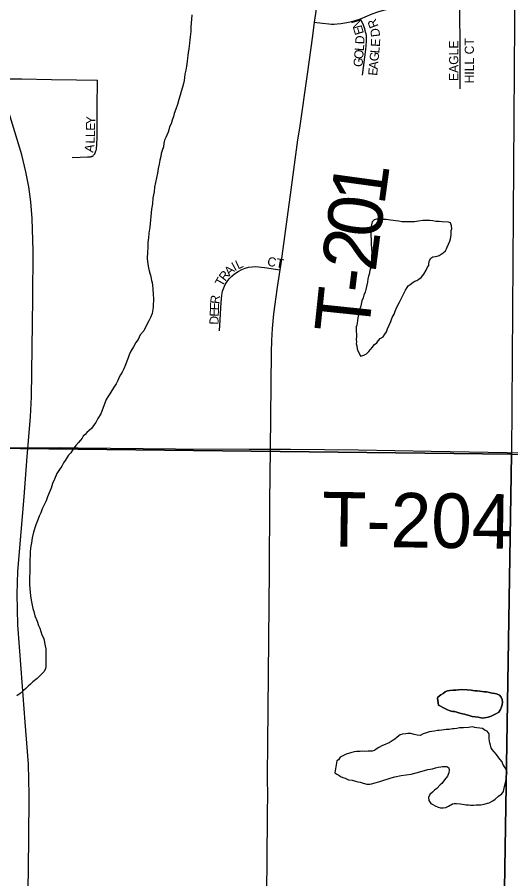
# Model space of a CAD drawing. Extents: x 0 to 68, y 0 to 52.9.
# Drawn here: x 43.794 to 44.473, y 38.666 to 39.851 of the extents above; entities that cross this region are included whole.
import ezdxf

# ---------------------------------------------------------------- set-up
doc = ezdxf.new("R2010")
doc.units = 0
for name, color, linetype in [('Default', 7, 'Continuous'), ('GM_X_Minor_Lake', 7, 'Continuous'), ('GM_X_Minor_River', 7, 'Continuous'), ('GM_X_Township_Road', 7, 'Continuous'), ('GM_X_Township_Road_Text', 7, 'Continuous'), ('GM_X_Township_Subdivision', 7, 'Continuous'), ('GM_X_Township_Subdivision_Text', 7, 'Continuous')]:
    doc.layers.add(name, color=color, linetype=linetype)

msp = doc.modelspace()

# ---------------------------------------------------------------- linework, layer by layer
at = {"layer": 'Default'}
for points in [[(44.4829, 40.5718), (44.4735, 39.2501), (43.1609, 39.2654), (43.1833, 40.5874)], [(43.1609, 39.2654), (44.4735, 39.2501), (44.4523, 37.939), (44.4103, 37.9396), (43.1327, 37.9528)], [(45.7998, 39.2161), (45.7821, 37.907), (45.7586, 37.9073), (44.4523, 37.939), (44.4735, 39.2501)]]:
    msp.add_lwpolyline(points, close=True, dxfattribs=at)
for points in [[(44.2659, 39.8493), (44.2819, 39.8561), (44.2897, 39.8588), (44.2976, 39.8611), (44.3057, 39.8629), (44.3138, 39.864), (44.322, 39.8646), (44.3463, 39.8653)], [(44.403, 39.7527), (44.4028, 39.7866), (44.4028, 39.8071), (44.4025, 39.8648)], [(44.2023, 39.8444), (44.2134, 39.8432), (44.2222, 39.8423), (44.2262, 39.8419), (44.2297, 39.842), (44.2336, 39.8422), (44.2386, 39.8428), (44.2469, 39.8442), (44.2558, 39.8461), (44.2659, 39.8493)], [(44.2687, 39.7718), (44.2732, 39.8068), (44.2743, 39.8181), (44.2743, 39.8206), (44.2741, 39.8237), (44.2739, 39.8261), (44.2735, 39.8287), (44.2729, 39.8309), (44.2716, 39.8352), (44.2698, 39.8404), (44.2659, 39.8493)], [(43.7391, 39.767), (43.7505, 39.7668), (43.7998, 39.7666), (43.8409, 39.7657), (43.8751, 39.7654), (43.9042, 39.7647)], [(43.8992, 39.662), (43.9003, 39.6636), (43.9009, 39.6649), (43.9014, 39.6662), (43.9018, 39.6673), (43.9023, 39.6685), (43.9026, 39.6695), (43.9027, 39.6701), (43.9028, 39.6712), (43.9029, 39.6721), (43.903, 39.6743), (43.9032, 39.6771), (43.9034, 39.6853), (43.9036, 39.704), (43.9038, 39.727), (43.9042, 39.7647)], [(43.8073, 38.5411), (43.8097, 38.7192), (43.8103, 38.7814), (43.8092, 38.8237), (43.8045, 38.8814), (43.7993, 38.9545), (43.7947, 39.0153), (43.7935, 39.0576), (43.7946, 39.0885), (43.8033, 39.1914), (43.8075, 39.2467), (43.812, 39.3017), (43.8135, 39.3289), (43.8152, 39.4639), (43.8154, 39.5301), (43.8142, 39.5746), (43.8124, 39.5973), (43.8095, 39.6179), (43.8056, 39.6387), (43.7999, 39.6618), (43.7776, 39.736)], [(43.8694, 39.6584), (43.8803, 39.6589), (43.8902, 39.6591), (43.8919, 39.6592), (43.8927, 39.6592), (43.8937, 39.6593), (43.8944, 39.6593), (43.8952, 39.6595), (43.8961, 39.6597), (43.8969, 39.6601), (43.8975, 39.6604), (43.898, 39.6608), (43.8987, 39.6614), (43.8992, 39.662)], [(43.6153, 39.2601), (43.7344, 39.2593), (43.8246, 39.2588), (43.8532, 39.2591), (43.8579, 39.2589)]]:
    msp.add_lwpolyline(points, dxfattribs=at)
at = {"layer": 'GM_X_Minor_Lake'}
for points in [[(44.387, 39.5695), (44.3784, 39.5697), (44.3784, 39.5697), (44.3739, 39.5703), (44.3694, 39.5704), (44.3654, 39.571), (44.3614, 39.5716), (44.3579, 39.5716), (44.3549, 39.5717), (44.3514, 39.5718), (44.3458, 39.5709), (44.3403, 39.57), (44.3338, 39.5696), (44.3278, 39.5697), (44.3227, 39.5698), (44.3188, 39.5709), (44.3147, 39.571), (44.3107, 39.5716), (44.3072, 39.5721), (44.3037, 39.5727), (44.3012, 39.5728), (44.2947, 39.5729), (44.2912, 39.5735), (44.2882, 39.5735), (44.2847, 39.5726), (44.2821, 39.5696), (44.281, 39.5656), (44.2805, 39.5632), (44.2804, 39.5601), (44.2804, 39.5576), (44.2803, 39.5551), (44.2803, 39.5526), (44.2802, 39.5496), (44.2806, 39.5466), (44.2805, 39.5421), (44.2805, 39.5391), (44.2809, 39.5331), (44.2813, 39.5275), (44.2811, 39.5215), (44.281, 39.5155), (44.2804, 39.51), (44.2798, 39.506), (44.2788, 39.503), (44.2782, 39.5005), (44.2776, 39.4975), (44.2771, 39.495), (44.276, 39.4915), (44.2754, 39.487), (44.2743, 39.481), (44.2732, 39.4765), (44.2721, 39.473), (44.2705, 39.4691), (44.2695, 39.4651), (44.2679, 39.4611), (44.2668, 39.4566), (44.2657, 39.4526), (44.2646, 39.4491), (44.2635, 39.4456), (44.263, 39.4421), (44.2624, 39.4376), (44.2618, 39.4341), (44.2612, 39.4306), (44.2607, 39.4276), (44.2601, 39.4251), (44.2601, 39.4221), (44.2604, 39.4121), (44.2598, 39.4081), (44.2602, 39.4046), (44.2601, 39.4021), (44.2606, 39.3991), (44.2615, 39.395), (44.262, 39.3925), (44.2639, 39.389), (44.2658, 39.3849), (44.2704, 39.3863), (44.2739, 39.3883), (44.2775, 39.3912), (44.2796, 39.3942), (44.2821, 39.3971), (44.2852, 39.4011), (44.2883, 39.4035), (44.2903, 39.406), (44.2929, 39.4094), (44.297, 39.4114), (44.2995, 39.4153), (44.3016, 39.4183), (44.3032, 39.4228), (44.3053, 39.4277), (44.3074, 39.4327), (44.3095, 39.4382), (44.3121, 39.4427), (44.3137, 39.4471), (44.3159, 39.4526), (44.3195, 39.4591), (44.3242, 39.4685), (44.3263, 39.473), (44.3279, 39.4759), (44.3299, 39.4794), (44.3315, 39.4819), (44.334, 39.4838)], [(44.334, 39.4838), (44.3381, 39.4868), (44.3407, 39.4882), (44.3432, 39.4892), (44.3462, 39.4911), (44.3493, 39.4931), (44.3529, 39.498), (44.356, 39.5035), (44.3581, 39.5074), (44.3597, 39.5099), (44.3597, 39.5124), (44.3608, 39.5164), (44.3624, 39.5199), (44.3654, 39.5218), (44.3689, 39.5223), (44.3715, 39.5227), (44.374, 39.5237), (44.377, 39.5251), (44.3796, 39.5271), (44.3826, 39.53), (44.3842, 39.5325), (44.3852, 39.535), (44.3889, 39.5434), (44.3895, 39.5464), (44.3906, 39.5514), (44.3907, 39.5544), (44.3907, 39.5579), (44.3913, 39.5604), (44.3909, 39.5644), (44.3899, 39.5685), (44.387, 39.5695)], [(44.4608, 38.905), (44.4614, 38.909), (44.4609, 38.9126), (44.4595, 38.9156), (44.457, 38.9187), (44.4531, 38.9202), (44.4506, 38.9208), (44.4471, 38.9214), (44.4431, 38.922), (44.4391, 38.923), (44.4366, 38.9231), (44.4331, 38.9237), (44.4301, 38.9242), (44.4265, 38.9243), (44.4235, 38.9244), (44.4205, 38.9249), (44.418, 38.9255), (44.4125, 38.9256), (44.4045, 38.9262), (44.397, 38.9254), (44.3935, 38.9255), (44.3889, 38.9251), (44.3854, 38.9246), (44.3824, 38.9232), (44.3798, 38.9207), (44.3763, 38.9188), (44.3722, 38.9159), (44.3717, 38.9144)], [(44.3717, 38.9144), (44.3722, 38.9159), (44.3763, 38.9188), (44.3798, 38.9207), (44.3824, 38.9232), (44.3854, 38.9246), (44.3889, 38.9251), (44.3935, 38.9255), (44.397, 38.9254), (44.4045, 38.9262), (44.4125, 38.9256), (44.418, 38.9255), (44.4205, 38.9249), (44.4235, 38.9244), (44.4265, 38.9243), (44.4301, 38.9242), (44.4331, 38.9237), (44.4366, 38.9231), (44.4391, 38.923), (44.4431, 38.922), (44.4471, 38.9214), (44.4506, 38.9208), (44.4531, 38.9202), (44.457, 38.9187), (44.4595, 38.9156), (44.4609, 38.9126), (44.4614, 38.909), (44.4608, 38.905), (44.4597, 38.9026), (44.4586, 38.8986), (44.4561, 38.8951), (44.453, 38.8932), (44.4495, 38.8912), (44.4454, 38.8898), (44.4414, 38.8884), (44.4363, 38.8875), (44.4338, 38.887), (44.4278, 38.8882), (44.4193, 38.8893), (44.4153, 38.8904), (44.4118, 38.8915), (44.4088, 38.8921), (44.4063, 38.8926), (44.4023, 38.8937), (44.3984, 38.8953), (44.3954, 38.8958), (44.3929, 38.8959), (44.3904, 38.8964), (44.3879, 38.8975), (44.3854, 38.8985), (44.3819, 38.9001), (44.3789, 38.9017), (44.376, 38.9032), (44.373, 38.9048), (44.3717, 38.9144)], [(44.3717, 38.9144), (44.373, 38.9048), (44.376, 38.9032), (44.3789, 38.9017), (44.3819, 38.9001), (44.3854, 38.8985), (44.3879, 38.8975), (44.3904, 38.8964), (44.3929, 38.8959), (44.3954, 38.8958), (44.3984, 38.8953), (44.4023, 38.8937), (44.4063, 38.8926), (44.4088, 38.8921), (44.4118, 38.8915), (44.4153, 38.8904), (44.4193, 38.8893), (44.4278, 38.8882), (44.4338, 38.887), (44.4363, 38.8875), (44.4414, 38.8884), (44.4454, 38.8898), (44.4495, 38.8912), (44.453, 38.8932), (44.4561, 38.8951), (44.4586, 38.8986), (44.4597, 38.9026), (44.4608, 38.905)], [(44.4058, 38.7687), (44.4088, 38.7682), (44.4113, 38.7676), (44.4143, 38.7676), (44.4173, 38.767), (44.4213, 38.7669), (44.4249, 38.7674), (44.4314, 38.7677), (44.4359, 38.7686), (44.4405, 38.77), (44.443, 38.7705), (44.4481, 38.7729), (44.4511, 38.7754), (44.4557, 38.7793), (44.4603, 38.7827), (44.4624, 38.7857), (44.4629, 38.7882), (44.464, 38.7926), (44.4651, 38.7961), (44.4657, 38.8001), (44.4668, 38.8041), (44.4668, 38.8081), (44.4674, 38.8116), (44.4665, 38.8152), (44.465, 38.8187), (44.4616, 38.8233), (44.4607, 38.8268), (44.4582, 38.8299), (44.4563, 38.8324), (44.4529, 38.837), (44.4499, 38.8406), (44.447, 38.8436), (44.4455, 38.8462), (44.4446, 38.8497), (44.4437, 38.8527), (44.4432, 38.8553), (44.4428, 38.8588), (44.4428, 38.8623), (44.4429, 38.8653), (44.44, 38.8689), (44.4375, 38.8699), (44.4335, 38.8725), (44.43, 38.8731), (44.426, 38.8737), (44.423, 38.8742), (44.42, 38.8748), (44.417, 38.8743), (44.4145, 38.8739), (44.4075, 38.8735), (44.4044, 38.8736), (44.4019, 38.8736), (44.3984, 38.8727), (44.3949, 38.8723), (44.3924, 38.8723), (44.3878, 38.8714), (44.3838, 38.871), (44.3808, 38.8706), (44.3773, 38.8701), (44.3743, 38.8697), (44.3718, 38.8697), (44.3677, 38.8688), (44.3642, 38.8684), (44.3602, 38.868), (44.3566, 38.8665), (44.3521, 38.8651), (44.3481, 38.8632), (44.344, 38.8633), (44.3395, 38.8644), (44.3351, 38.8655), (44.331, 38.8655), (44.328, 38.8651), (44.3235, 38.8647), (44.3205, 38.8637), (44.3164, 38.8608), (44.3133, 38.8579), (44.3108, 38.8564), (44.3082, 38.8545), (44.3052, 38.853), (44.3007, 38.8511), (44.2951, 38.8487), (44.291, 38.8463), (44.2875, 38.8443), (44.2849, 38.8424), (44.2819, 38.8414), (44.2789, 38.8415), (44.2764, 38.8416), (44.2719, 38.8411), (44.2693, 38.8412), (44.2653, 38.8408), (44.2628, 38.8408), (44.2603, 38.8409), (44.2573, 38.8404), (44.2538, 38.8395), (44.2462, 38.8372), (44.2381, 38.8333), (44.2355, 38.8293), (44.2333, 38.8281)], [(44.2333, 38.8281), (44.2306, 38.8114), (44.2331, 38.8098), (44.2361, 38.8083), (44.2385, 38.8067), (44.2415, 38.8052), (44.245, 38.8041), (44.2495, 38.802), (44.2545, 38.8014), (44.259, 38.8003), (44.262, 38.7992), (44.2655, 38.7986), (44.2695, 38.7976), (44.2745, 38.796), (44.2785, 38.7959), (44.281, 38.7963), (44.286, 38.7977), (44.2926, 38.7996), (44.3082, 38.8048), (44.3133, 38.8062), (44.3219, 38.808), (44.3289, 38.8089), (44.3354, 38.8098), (44.3475, 38.813), (44.3586, 38.8163), (44.3647, 38.8172), (44.3692, 38.8186), (44.3728, 38.8196), (44.3763, 38.82), (44.3788, 38.8204), (44.3823, 38.8204), (44.3848, 38.8203), (44.3873, 38.8183), (44.3877, 38.8152), (44.3876, 38.8117), (44.3866, 38.8093), (44.3855, 38.8068), (44.3814, 38.8018), (44.3778, 38.7969), (44.3753, 38.7949), (44.3711, 38.79), (44.3676, 38.7876), (44.365, 38.7851), (44.3614, 38.7817), (44.3594, 38.7777), (44.3598, 38.7737), (44.3627, 38.7696), (44.3652, 38.7681), (44.3687, 38.766), (44.3726, 38.7644), (44.3761, 38.7633), (44.3796, 38.7633), (44.3832, 38.7637), (44.3867, 38.7656), (44.3923, 38.769), (44.3948, 38.7695), (44.3978, 38.7694), (44.4033, 38.7688), (44.4058, 38.7687)]]:
    msp.add_lwpolyline(points, dxfattribs=at)
at = {"layer": 'GM_X_Minor_River'}
for points in [[(44.034, 39.8545), (44.0327, 39.8375), (44.0326, 39.8319), (44.032, 39.8279), (44.0314, 39.8244), (44.0313, 39.8204), (44.0308, 39.8159), (44.0302, 39.8119), (44.0296, 39.8074), (44.029, 39.8029), (44.0284, 39.7989), (44.0278, 39.7949), (44.0272, 39.7904), (44.0266, 39.7839), (44.0255, 39.7784), (44.0244, 39.7729), (44.0238, 39.7684), (44.0232, 39.7644), (44.0226, 39.7604), (44.021, 39.7549), (44.0194, 39.749), (44.0178, 39.744), (44.0161, 39.738), (44.014, 39.7315), (44.0119, 39.725), (44.0097, 39.7191), (44.0086, 39.7146), (44.007, 39.7096), (44.0054, 39.7046), (44.0033, 39.7006), (44.0022, 39.6966), (44.0012, 39.6932), (43.9996, 39.6892), (43.998, 39.6857), (43.9964, 39.6822), (43.9954, 39.6782), (43.9947, 39.6732), (43.9931, 39.6682), (43.9915, 39.6638), (43.991, 39.6598), (43.9899, 39.6548), (43.9887, 39.6493), (43.9876, 39.6433), (43.9865, 39.6368), (43.9854, 39.6303), (43.9837, 39.6238), (43.9826, 39.6173), (43.982, 39.6113), (43.9803, 39.6028), (43.9796, 39.5948), (43.9785, 39.5873), (43.9759, 39.5623), (43.9748, 39.5543), (43.9741, 39.5478), (43.9735, 39.5412), (43.9734, 39.5347), (43.9727, 39.5282), (43.9726, 39.5192), (43.9734, 39.5117), (43.9743, 39.5066), (43.9752, 39.5026), (43.9762, 39.4991), (43.9771, 39.4965), (43.978, 39.492), (43.9785, 39.489), (43.9794, 39.4865), (43.9798, 39.4824), (43.9802, 39.4774), (43.9806, 39.4699), (43.981, 39.4644), (43.9809, 39.4604), (43.9808, 39.4574), (43.9808, 39.4528), (43.9802, 39.4493), (43.9791, 39.4438), (43.9769, 39.4384), (43.9748, 39.4334), (43.9717, 39.4274), (43.968, 39.42), (43.9629, 39.4141), (43.9598, 39.4081), (43.9567, 39.4037), (43.9535, 39.3977), (43.9499, 39.3918), (43.9478, 39.3868), (43.9462, 39.3828), (43.9446, 39.3783), (43.9425, 39.3729), (43.9404, 39.3674), (43.9378, 39.3629), (43.9357, 39.3595), (43.9341, 39.356), (43.932, 39.3515)], [(43.932, 39.3515), (43.9299, 39.347), (43.9268, 39.3426), (43.9237, 39.3376), (43.9211, 39.3332), (43.9185, 39.3292), (43.916, 39.3253), (43.9085, 39.3058), (43.9044, 39.2994), (43.9018, 39.2939), (43.8987, 39.2895), (43.8961, 39.286), (43.8925, 39.2826), (43.8895, 39.2797), (43.8869, 39.2772), (43.8843, 39.2747), (43.8828, 39.2723), (43.8807, 39.2693), (43.8781, 39.2663), (43.8745, 39.2619), (43.872, 39.2589), (43.8699, 39.2555), (43.8673, 39.252), (43.8642, 39.2486), (43.8617, 39.2451), (43.8596, 39.2416), (43.8575, 39.2382), (43.8549, 39.2337), (43.8518, 39.2288), (43.8482, 39.2233), (43.845, 39.2159), (43.8424, 39.2099), (43.8402, 39.2034), (43.8376, 39.1969), (43.8355, 39.1915), (43.8334, 39.186), (43.8308, 39.1805), (43.8281, 39.1751), (43.826, 39.1696), (43.8239, 39.1646), (43.8218, 39.1596), (43.8192, 39.1527), (43.8159, 39.1427), (43.8143, 39.1352), (43.8131, 39.1282), (43.812, 39.1212), (43.8114, 39.1147), (43.8113, 39.1102), (43.8112, 39.1057), (43.8111, 39.1007), (43.811, 39.0972), (43.8109, 39.0927), (43.8108, 39.0877), (43.8107, 39.0806), (43.8106, 39.0756), (43.8105, 39.0701), (43.8109, 39.0651), (43.8117, 39.055), (43.813, 39.049), (43.8144, 39.0424), (43.8153, 39.0379), (43.8167, 39.0334), (43.8181, 39.0278), (43.821, 39.0202), (43.8229, 39.0142), (43.8248, 39.0106), (43.8262, 39.0061), (43.8276, 39.0016), (43.8296, 38.9975), (43.8305, 38.994), (43.8314, 38.9909), (43.8323, 38.9864), (43.8328, 38.9824), (43.8331, 38.9754), (43.833, 38.9694), (43.8329, 38.9628), (43.8328, 38.9578), (43.8327, 38.9548), (43.8301, 38.9504), (43.826, 38.9464), (43.8209, 38.9415), (43.8153, 38.9366), (43.8117, 38.9337), (43.8086, 38.9307), (43.8056, 38.9278), (43.8025, 38.9248), (43.7979, 38.9209), (43.7933, 38.9175)]]:
    msp.add_lwpolyline(points, dxfattribs=at)
at = {"layer": 'GM_X_Township_Road'}
for points in [[(44.2126, 39.9141), (44.2023, 39.8444)], [(44.2023, 39.8444), (44.1997, 39.8257), (44.1925, 39.7729), (44.1819, 39.6989)], [(44.1819, 39.6989), (44.1794, 39.6827), (44.1702, 39.6137), (44.1562, 39.5124), (44.1549, 39.5036)], [(44.1549, 39.5036), (44.1513, 39.4799), (44.1463, 39.4434), (44.1442, 39.4231), (44.1433, 39.4067), (44.143, 39.3903), (44.1418, 39.2568)], [(43.8579, 39.2589), (43.8777, 39.2587)], [(43.8777, 39.2587), (44.0115, 39.2574), (44.1126, 39.257), (44.1418, 39.2568)], [(44.1418, 39.2568), (44.1409, 39.1843), (44.1401, 39.09), (44.1379, 38.8521), (44.1376, 38.8077), (44.138, 38.7767), (44.1376, 38.7612), (44.1368, 38.6836), (44.1357, 38.6017), (44.1348, 38.4829), (44.1338, 38.4295), (44.1326, 38.3229), (44.1314, 38.2573), (44.1303, 38.1835), (44.1274, 38.0358), (44.126, 37.9797), (44.1264, 37.9556), (44.1266, 37.9518), (44.1273, 37.949), (44.1301, 37.9455)], [(44.1418, 39.2568), (44.1694, 39.2568), (44.2632, 39.2561), (44.363, 39.2544), (44.4678, 39.2526), (44.6184, 39.2499), (44.7894, 39.2463), (44.806, 39.2462)]]:
    msp.add_lwpolyline(points, dxfattribs=at)
at = {"layer": 'GM_X_Township_Subdivision'}
msp.add_lwpolyline([(44.0717, 39.4196), (44.0728, 39.4351), (44.0742, 39.4589), (44.0751, 39.4687), (44.0762, 39.4744), (44.0777, 39.479), (44.0798, 39.4835), (44.0824, 39.4877), (44.0854, 39.4916), (44.0889, 39.4951), (44.0927, 39.4982), (44.0974, 39.5016), (44.1025, 39.5043), (44.1071, 39.5061), (44.1118, 39.5073), (44.1167, 39.508), (44.1216, 39.5082), (44.1257, 39.508), (44.1339, 39.5069), (44.1549, 39.5036)], dxfattribs=at)

# ---------------------------------------------------------------- texts
at = {"layer": 'Default'}
for s, rotation, p in [('N', 105.7593, (44.2682, 39.8377)), ('R', 110.8408, (44.2908, 39.8391)), ('E', 107.0975, (44.2708, 39.8294)), ('D', 97.1992, (44.293, 39.825)), ('D', 88.6753, (44.2711, 39.8141)), ('L', 84.9097, (44.2703, 39.8044)), ('E', 86.5313, (44.2924, 39.8104)), ('EAGLE', 90, (44.4003, 39.7636)), ('HILL CT', 90, (44.4218, 39.7603)), ('O', 84.9023, (44.2693, 39.7934)), ('G', 84.6088, (44.2905, 39.7903)), ('L', 84.9344, (44.2916, 39.8013)), ('G', 84.9006, (44.2684, 39.7825)), ('A', 84.5638, (44.2895, 39.7793)), ('E', 84.5558, (44.2887, 39.7705)), ('E', 88.7016, (43.9006, 39.6951)), ('Y', 88.7104, (43.9008, 39.7039)), ('L', 88.6879, (43.9004, 39.6863)), ('L', 88.2981, (43.9001, 39.6774)), ('A', 80.1604, (43.898, 39.6646))]:
    msp.add_text(s, height=0.0125, rotation=rotation, dxfattribs=at).set_placement(p)
at = {"layer": 'GM_X_Township_Road_Text'}
for s, rotation, p in [('1', 82.1694, (44.2986, 39.5913)), ('0', 82.2695, (44.2924, 39.5455)), ('2', 82.6478, (44.2865, 39.4998)), ('-', 83.0589, (44.2828, 39.4694)), ('T', 84.028, (44.277, 39.4139)), ('T-204', 359.2261, (44.2123, 39.1234))]:
    msp.add_text(s, height=0.075, rotation=rotation, dxfattribs=at).set_placement(p)
at = {"layer": 'GM_X_Township_Subdivision_Text'}
for s, rotation, p in [('L', 25.0251, (44.0974, 39.5042)), ('CT', 349.9964, (44.1369, 39.5096)), ('A', 43.0677, (44.0855, 39.4946)), ('I', 28.9909, (44.0928, 39.5017)), ('T', 60.7702, (44.0757, 39.4799)), ('R', 52.1782, (44.0797, 39.4872)), ('R', 84.6978, (44.0715, 39.4565)), ('E', 87.7039, (44.0711, 39.4479)), ('E', 87.7039, (44.0708, 39.4391)), ('D', 87.7041, (44.0704, 39.4281))]:
    msp.add_text(s, height=0.0125, rotation=rotation, dxfattribs=at).set_placement(p)

doc.saveas('drawing.dxf')
